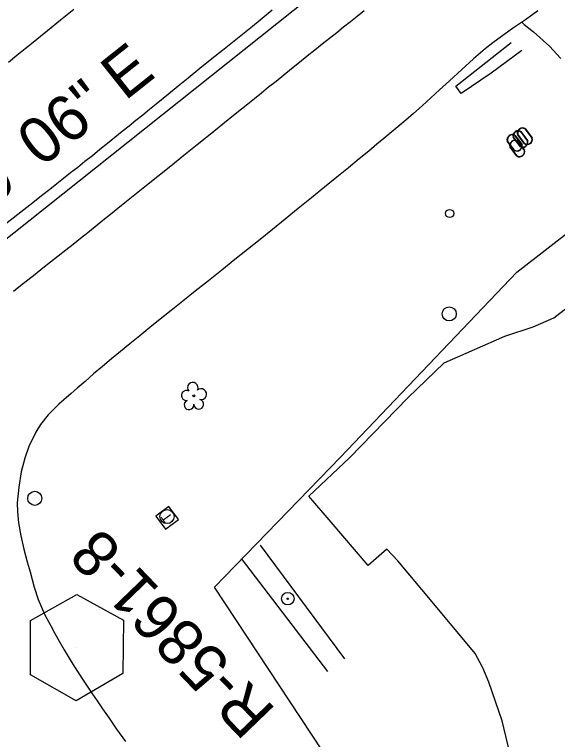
# Model space of a CAD drawing. Extents: x 471894 to 476235, y 503501 to 507878.
# Drawn here: x 473749.9 to 473939.4, y 506128.6 to 506381.3 of the extents above; entities that cross this region are included whole.
import ezdxf

# ---------------------------------------------------------------- set-up
doc = ezdxf.new("R2010")
doc.units = 0
for name, color, linetype in [('CTL Primary Horizontal and Vertical CELL', 7, 'Continuous'), ('CTL Primary Horizontal and Vertical Text', 7, 'Continuous'), ('Exist Horizontal Alignment', 7, 'Continuous'), ('Exist Horizontal Alignment Direction Label', 7, 'Continuous'), ('Exist Other Culture Fence Line', 7, 'Continuous'), ('Exist Other Culture Gas Pump or Vent CELL', 7, 'Continuous'), ('Exist Other Culture Sign', 7, 'Continuous'), ('Exist Other Culture Sign Post CELL', 7, 'Continuous'), ('Exist Roads EOP', 7, 'Continuous'), ('Exist Roads EOP Other', 7, 'Continuous'), ('Exist Structure Minor Paved Ditch or Gutter', 7, 'Continuous'), ('Exist Utilities Other Pole CELL', 7, 'Continuous'), ('Exist Utilities Telephone Pedestal CELL', 7, 'Continuous'), ('Exist Utilities Water Meter CELL', 7, 'Continuous'), ('Exist Vegetation Tree CELL', 7, 'Continuous')]:
    doc.layers.add(name, color=color, linetype=linetype)

msp = doc.modelspace()

# ---------------------------------------------------------------- linework, layer by layer
at = {"layer": 'CTL Primary Horizontal and Vertical CELL'}
msp.add_line((473771.63, 506160.66), (473771.63, 506160.66), dxfattribs=at)
msp.add_lwpolyline([(473755.47, 506170.02), (473771.72, 506179.08), (473787.97, 506170.14), (473787.72, 506151.52), (473771.47, 506142.08), (473755.47, 506151.14)], close=True, dxfattribs=at)
at = {"layer": 'Exist Horizontal Alignment'}
msp.add_line((473294.53, 505943.19), (474190.95, 506656.19), dxfattribs=at)
at = {"layer": 'Exist Other Culture Fence Line'}
msp.add_lwpolyline([(473913.78, 506041.26), (473868.72, 506107.56), (473819.7, 506181.61), (473863.62, 506226.96), (473925.15, 506291.5), (473965.74, 506322.98)], dxfattribs=at)
at = {"layer": 'Exist Other Culture Gas Pump or Vent CELL'}
msp.add_circle((473901.76, 506311.93), 1.44, dxfattribs=at)
at = {"layer": 'Exist Other Culture Sign'}
for p, q in [((473835.69, 506196.27), (473865.06, 506156.67)), ((473859.27, 506152.28), (473829.11, 506191.64))]:
    msp.add_line(p, q, dxfattribs=at)
at = {"layer": 'Exist Other Culture Sign Post CELL'}
for radius in [2.18, 0.24]:
    msp.add_circle((473845.27, 506177.63), radius, dxfattribs=at)
at = {"layer": 'Exist Roads EOP'}
for points in [[(473839.86, 506382.79), (473836.38, 506379.94), (473832.91, 506377.12), (473829.44, 506374.31), (473825.97, 506371.54), (473822.51, 506368.79), (473818.8, 506365.83), (473814.58, 506362.43), (473810.47, 506359.1), (473807.06, 506356.34), (473803.61, 506353.53), (473799.36, 506350.07), (473797.02, 506348.17), (473794.67, 506346.26), (473792.31, 506344.35), (473789.92, 506342.43), (473787.49, 506340.48), (473784.99, 506338.46), (473782.41, 506336.38), (473779.75, 506334.23), (473777.09, 506332.09), (473774.49, 506330.01), (473771.97, 506328), (473769.51, 506326.06), (473767.08, 506324.15), (473764.67, 506322.25), (473762.26, 506320.35), (473759.86, 506318.46), (473755.27, 506314.85), (473751.06, 506311.56), (473746.8, 506308.23)], [(473747.79, 506364.72), (473750.73, 506367.09), (473753.63, 506369.43), (473756.4, 506371.68), (473759.01, 506373.79), (473761.45, 506375.77), (473765.95, 506379.41), (473770.59, 506383.17)], [(473749.58, 506284.89), (473752.01, 506286.81), (473754.53, 506288.79), (473757.13, 506290.84), (473759.81, 506292.95), (473762.52, 506295.08), (473765.18, 506297.17), (473767.79, 506299.23), (473770.35, 506301.26), (473772.9, 506303.29), (473775.48, 506305.35), (473778.1, 506307.44), (473780.76, 506309.58), (473783.39, 506311.69), (473785.93, 506313.74), (473788.4, 506315.72), (473790.78, 506317.62), (473795.4, 506321.34), (473799.92, 506324.97), (473804.44, 506328.61), (473809.06, 506332.33), (473813.69, 506336.04), (473818.21, 506339.65), (473822.62, 506343.18), (473826.92, 506346.63), (473831.34, 506350.18), (473833.67, 506352.06), (473836.09, 506354.02), (473838.59, 506356.04), (473841.18, 506358.12), (473843.85, 506360.28), (473846.61, 506362.49), (473849.38, 506364.72), (473852.09, 506366.89), (473854.74, 506369.01), (473857.33, 506371.07), (473859.87, 506373.09), (473862.35, 506375.07), (473864.77, 506377), (473867.14, 506378.89), (473869.5, 506380.77), (473871.88, 506382.68)], [(473932.58, 506382.58), (473928.18, 506379.42), (473923.72, 506376.45), (473919.82, 506373.7), (473916.87, 506371.42), (473914.19, 506369.29), (473910.13, 506365.84), (473905.98, 506362.13), (473901.65, 506358.2), (473898.24, 506355.07), (473895.24, 506352.31), (473892.14, 506349.51), (473889.16, 506346.85), (473886.52, 506344.53), (473882.32, 506340.96), (473878.79, 506338.05), (473876.39, 506336.08), (473873.52, 506333.72), (473870.16, 506330.96), (473866.43, 506327.89), (473862.42, 506324.61), (473858.12, 506321.12), (473853.55, 506317.42), (473848.9, 506313.65), (473844.35, 506309.98), (473839.92, 506306.39), (473835.6, 506302.9), (473831.28, 506299.41), (473826.84, 506295.85), (473822.29, 506292.22), (473817.62, 506288.51), (473813.02, 506284.86), (473808.68, 506281.41), (473804.6, 506278.16), (473800.77, 506275.1), (473797.13, 506272.17), (473793.61, 506269.33), (473790.21, 506266.55), (473786.93, 506263.86), (473783.74, 506261.21), (473780.61, 506258.59), (473777.54, 506255.98), (473774.54, 506253.4), (473771.83, 506251.07), (473769.69, 506249.23), (473765.42, 506245.51), (473761.72, 506241.76), (473758.99, 506238.4), (473757.34, 506235.69), (473754.93, 506230.66), (473753.48, 506226.63), (473752.31, 506221.89), (473751.43, 506216.49), (473750.91, 506211.07), (473750.94, 506207.96), (473751.37, 506204.04), (473752.15, 506199.6), (473753.24, 506194.93), (473754.4, 506190.55), (473755.37, 506186.96), (473756.79, 506181.71), (473758.16, 506177.33), (473760.53, 506172.02), (473762.55, 506168.22), (473763.93, 506165.72), (473765.54, 506162.82), (473767.27, 506159.8), (473768.96, 506156.94), (473770.62, 506154.24), (473773.87, 506149.26), (473777.14, 506144.4), (473778.8, 506141.99), (473780.66, 506139.3), (473782.91, 506136.04), (473785.56, 506132.21), (473788.61, 506127.81)]]:
    msp.add_lwpolyline(points, dxfattribs=at)
at = {"layer": 'Exist Roads EOP Other'}
for points in [[(473927.08, 506378.52), (473927.74, 506377.84), (473931.03, 506375.27), (473936.64, 506370.23), (473940.55, 506365.99)], [(473924.26, 506117.61), (473920.13, 506135.01), (473915.4, 506148.55), (473913.31, 506153.52), (473910.68, 506158.56), (473896.2, 506175.86), (473883.67, 506190.82), (473879.78, 506194.93), (473873.32, 506189.22), (473860.43, 506204.37), (473852.66, 506213.43), (473866.93, 506226.92), (473887.22, 506247.64), (473899.86, 506259.92), (473921.01, 506269.22), (473930.84, 506272.39), (473938.09, 506275.54), (473942.77, 506279.15)]]:
    msp.add_lwpolyline(points, dxfattribs=at)
at = {"layer": 'Exist Structure Minor Paved Ditch or Gutter'}
msp.add_lwpolyline([(473926.94, 506368.72), (473916.2, 506360.84), (473905.72, 506353.72), (473903.95, 506356.34), (473923.21, 506371.55)], dxfattribs=at)
at = {"layer": 'Exist Utilities Other Pole CELL'}
for centre in [(473901.59, 506276.92), (473756.99, 506212.63), (473803.14, 506206.28)]:
    msp.add_circle(centre, 2.46, dxfattribs=at)
at = {"layer": 'Exist Utilities Telephone Pedestal CELL'}
msp.add_line((473803.2, 506205.74), (473803.2, 506205.74), dxfattribs=at)
msp.add_lwpolyline([(473807.09, 506205.23), (473803.77, 506209.73), (473799.27, 506206.41), (473802.59, 506201.91), (473807.09, 506205.23)], dxfattribs=at)
at = {"layer": 'Exist Utilities Water Meter CELL'}
for p, q in [((473926.47, 506337.9), (473926.47, 506337.9)), ((473928, 506338.88), (473928, 506338.88)), ((473924.42, 506336.57), (473924.42, 506336.57)), ((473925.33, 506334.59), (473925.33, 506334.59))]:
    msp.add_line(p, q, dxfattribs=at)
for points in [[(473927.96, 506336.31), (473925.51, 506339.6)], [(473926.52, 506340.47), (473928.93, 506337.18)], [(473926.63, 506340.55), (473929.04, 506337.27)], [(473928.04, 506341.45), (473930.47, 506338.18)], [(473928.15, 506341.53), (473930.58, 506338.26)], [(473924.3, 506333.92), (473921.81, 506337.18)], [(473924.41, 506334.01), (473921.92, 506337.26)], [(473926.31, 506335.25), (473923.87, 506338.55)], [(473926.42, 506335.33), (473923.98, 506338.63)], [(473924.42, 506339.14), (473926.89, 506335.9)], [(473924.53, 506339.23), (473927, 506335.99)], [(473925.35, 506337.16), (473927.81, 506333.9)], [(473927.85, 506336.23), (473925.4, 506339.52)], [(473925.46, 506337.24), (473927.92, 506333.99)], [(473925.2, 506331.94), (473922.73, 506335.21)], [(473925.31, 506332.02), (473922.84, 506335.3)]]:
    msp.add_lwpolyline(points, dxfattribs=at)
for centre, radius, start, end in [((473925.69, 506338.95), 1.86, 59.5398, 192.3411), ((473925.69, 506338.94), 1.73, 61.6627, 190.1441), ((473927.21, 506339.93), 1.86, 59.8187, 192.62), ((473927.22, 506339.92), 1.73, 61.9416, 190.423), ((473923.62, 506337.61), 1.86, 60.5851, 193.3865), ((473923.62, 506337.6), 1.73, 62.708, 191.1894), ((473924.54, 506335.63), 1.86, 60.1901, 192.9915), ((473924.55, 506335.62), 1.73, 62.313, 190.7944), ((473927.23, 506336.86), 1.86, 240.01, 12.6701), ((473927.24, 506336.85), 1.73, 241.4889, 11.2346), ((473928.77, 506337.85), 1.86, 240.2889, 12.949), ((473928.78, 506337.84), 1.73, 241.7678, 11.5134), ((473925.2, 506335.55), 1.86, 241.0554, 13.7155), ((473925.21, 506335.54), 1.73, 242.5343, 12.2799), ((473926.11, 506333.56), 1.86, 240.6604, 13.3205), ((473926.12, 506333.55), 1.73, 242.1393, 11.8849)]:
    msp.add_arc(centre, radius, start, end, dxfattribs=at)
at = {"layer": 'Exist Vegetation Tree CELL'}
msp.add_line((473812.51, 506248.34), (473812.51, 506248.34), dxfattribs=at)
msp.add_circle((473812.51, 506248.34), 0.326, dxfattribs=at)
for centre, radius, start, end in [((473812.13, 506251.21), 1.86, 330.1651, 219.7134), ((473809.91, 506248.49), 1.73, 62.6636, 279.3457), ((473815.06, 506248.93), 1.9, 257.1011, 134.1999), ((473810.81, 506245.22), 1.69, 111.5671, 6.231), ((473814.19, 506245.44), 1.7, 181.2822, 74.56)]:
    msp.add_arc(centre, radius, start, end, dxfattribs=at)

# ---------------------------------------------------------------- texts
at = {"layer": 'CTL Primary Horizontal and Vertical Text'}
msp.add_text('R-5861-8', height=16, rotation=133.8986, dxfattribs=at).set_placement((473841.55, 506138.8))
at = {"layer": 'Exist Horizontal Alignment Direction Label'}
msp.add_text('N 51%%d 30\' 06" E', height=16, rotation=38.4983, dxfattribs=at).set_placement((473686.06, 506269.51))
at = {"layer": 'Exist Utilities Telephone Pedestal CELL'}
msp.add_text('T', height=3.42, rotation=126.3877, dxfattribs=at).set_placement((473805.25, 506205.85))

doc.saveas('drawing.dxf')
